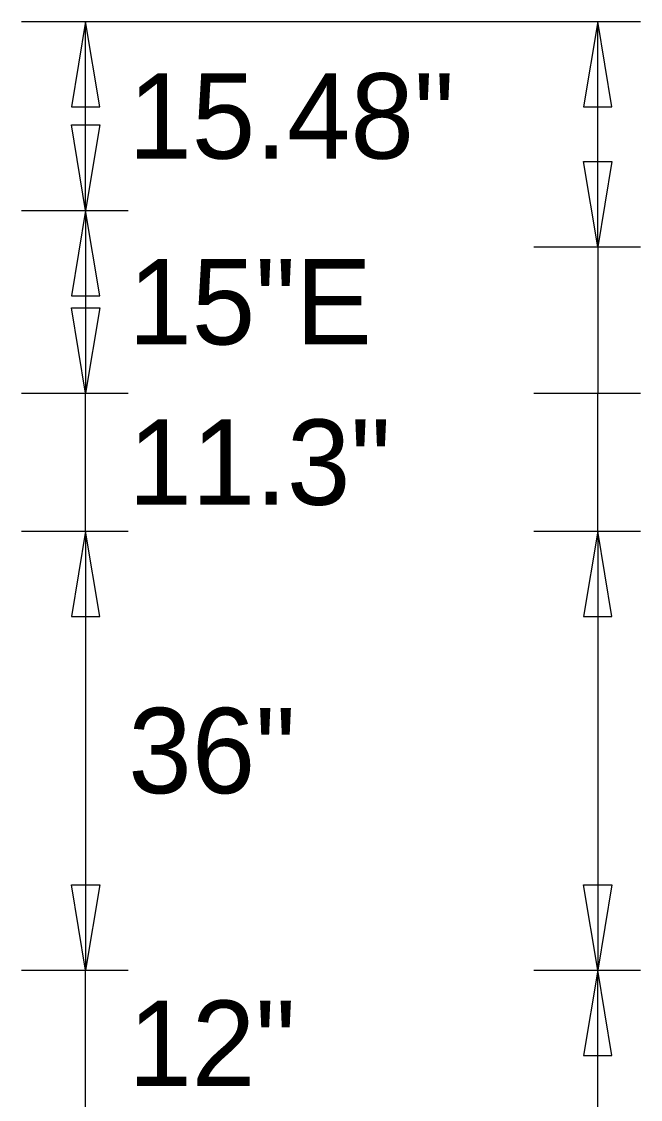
# Model space of a CAD drawing. Extents: x 2150010 to 2150174, y 145114 to 145224.
# Drawn here: x 2150047.75 to 2150051.98, y 145150.52 to 145157.88 of the extents above; entities that cross this region are included whole.
import ezdxf

# ---------------------------------------------------------------- set-up
doc = ezdxf.new("R2010")
doc.units = 0
doc.layers.add('GSDIMS', color=7, linetype='Continuous')

msp = doc.modelspace()

# ---------------------------------------------------------------- linework, layer by layer
at = {"layer": 'GSDIMS'}
for p, q in [((2150047.7493, 145157.8829), (2150048.4784, 145157.8829)), ((2150047.7493, 145157.8829), (2150051.2493, 145157.8829)), ((2150048.1868, 145156.5928), (2150048.1868, 145157.8829)), ((2150051.2493, 145157.8829), (2150051.9784, 145157.8829)), ((2150051.6868, 145156.3428), (2150051.6868, 145157.8829)), ((2150047.7493, 145156.5928), (2150048.4784, 145156.5928)), ((2150047.7493, 145156.5928), (2150048.4784, 145156.5928)), ((2150048.1868, 145156.5928), (2150048.1868, 145155.3428)), ((2150051.2493, 145156.3428), (2150051.9784, 145156.3428)), ((2150051.2493, 145156.3428), (2150051.9784, 145156.3428)), ((2150051.6868, 145156.3428), (2150051.6868, 145155.3428)), ((2150047.7493, 145155.3428), (2150048.4784, 145155.3428)), ((2150047.7493, 145155.3428), (2150048.4784, 145155.3428)), ((2150048.1868, 145154.4011), (2150048.1868, 145155.3428)), ((2150051.2493, 145155.3428), (2150051.9784, 145155.3428)), ((2150051.2493, 145155.3428), (2150051.9784, 145155.3428)), ((2150051.6868, 145154.4011), (2150051.6868, 145155.3428)), ((2150047.7493, 145154.4011), (2150048.4784, 145154.4011)), ((2150047.7493, 145154.4011), (2150048.4784, 145154.4011)), ((2150048.1868, 145154.4011), (2150048.1868, 145151.401)), ((2150051.2493, 145154.4011), (2150051.9784, 145154.4011)), ((2150051.2493, 145154.4011), (2150051.9784, 145154.4011)), ((2150051.6868, 145154.4011), (2150051.6868, 145151.401)), ((2150047.7493, 145151.401), (2150048.4784, 145151.401)), ((2150047.7493, 145151.401), (2150048.4784, 145151.401)), ((2150048.1868, 145150.401), (2150048.1868, 145151.401)), ((2150051.2493, 145151.401), (2150051.9784, 145151.401)), ((2150051.2493, 145151.401), (2150051.9784, 145151.401)), ((2150051.6868, 145143.8829), (2150051.6868, 145151.401))]:
    msp.add_line(p, q, dxfattribs=at)
for points in [[(2150048.1868, 145157.8829), (2150048.0895, 145157.2996), (2150048.284, 145157.2996)], [(2150051.6868, 145157.8829), (2150051.5895, 145157.2996), (2150051.784, 145157.2996)], [(2150048.1868, 145156.5928), (2150048.0895, 145157.1762), (2150048.284, 145157.1762)], [(2150051.6868, 145156.3428), (2150051.5895, 145156.9262), (2150051.784, 145156.9262)], [(2150048.1868, 145156.5928), (2150048.0895, 145156.0095), (2150048.284, 145156.0095)], [(2150048.1868, 145155.3428), (2150048.0895, 145155.9262), (2150048.284, 145155.9262)], [(2150048.1868, 145154.4011), (2150048.0895, 145153.8178), (2150048.284, 145153.8178)], [(2150051.6868, 145154.4011), (2150051.5895, 145153.8178), (2150051.784, 145153.8178)], [(2150048.1868, 145151.401), (2150048.0895, 145151.9843), (2150048.284, 145151.9843)], [(2150051.6868, 145151.401), (2150051.5895, 145151.9843), (2150051.784, 145151.9843)], [(2150051.6868, 145151.401), (2150051.5895, 145150.8177), (2150051.784, 145150.8177)]]:
    msp.add_lwpolyline(points, close=True, dxfattribs=at)

# ---------------------------------------------------------------- texts
for s, p in [('15.48"', (2150048.4785, 145156.9462)), ('15"E', (2150048.4785, 145155.6762)), ('11.3"', (2150048.4785, 145154.5803)), ('36"', (2150048.4785, 145152.6094)), ('12"', (2150048.4785, 145150.6094))]:
    msp.add_text(s, height=0.58333, dxfattribs=at).set_placement(p)

doc.saveas('drawing.dxf')
